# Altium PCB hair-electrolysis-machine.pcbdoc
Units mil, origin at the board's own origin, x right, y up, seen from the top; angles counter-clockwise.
Board outline 3248.4 x 4021.2 mil, 2 copper layers (Top Layer, Bottom Layer), stack 1.5 mil thick; 83 components, 64 nets, 277 pads, 40 vias.
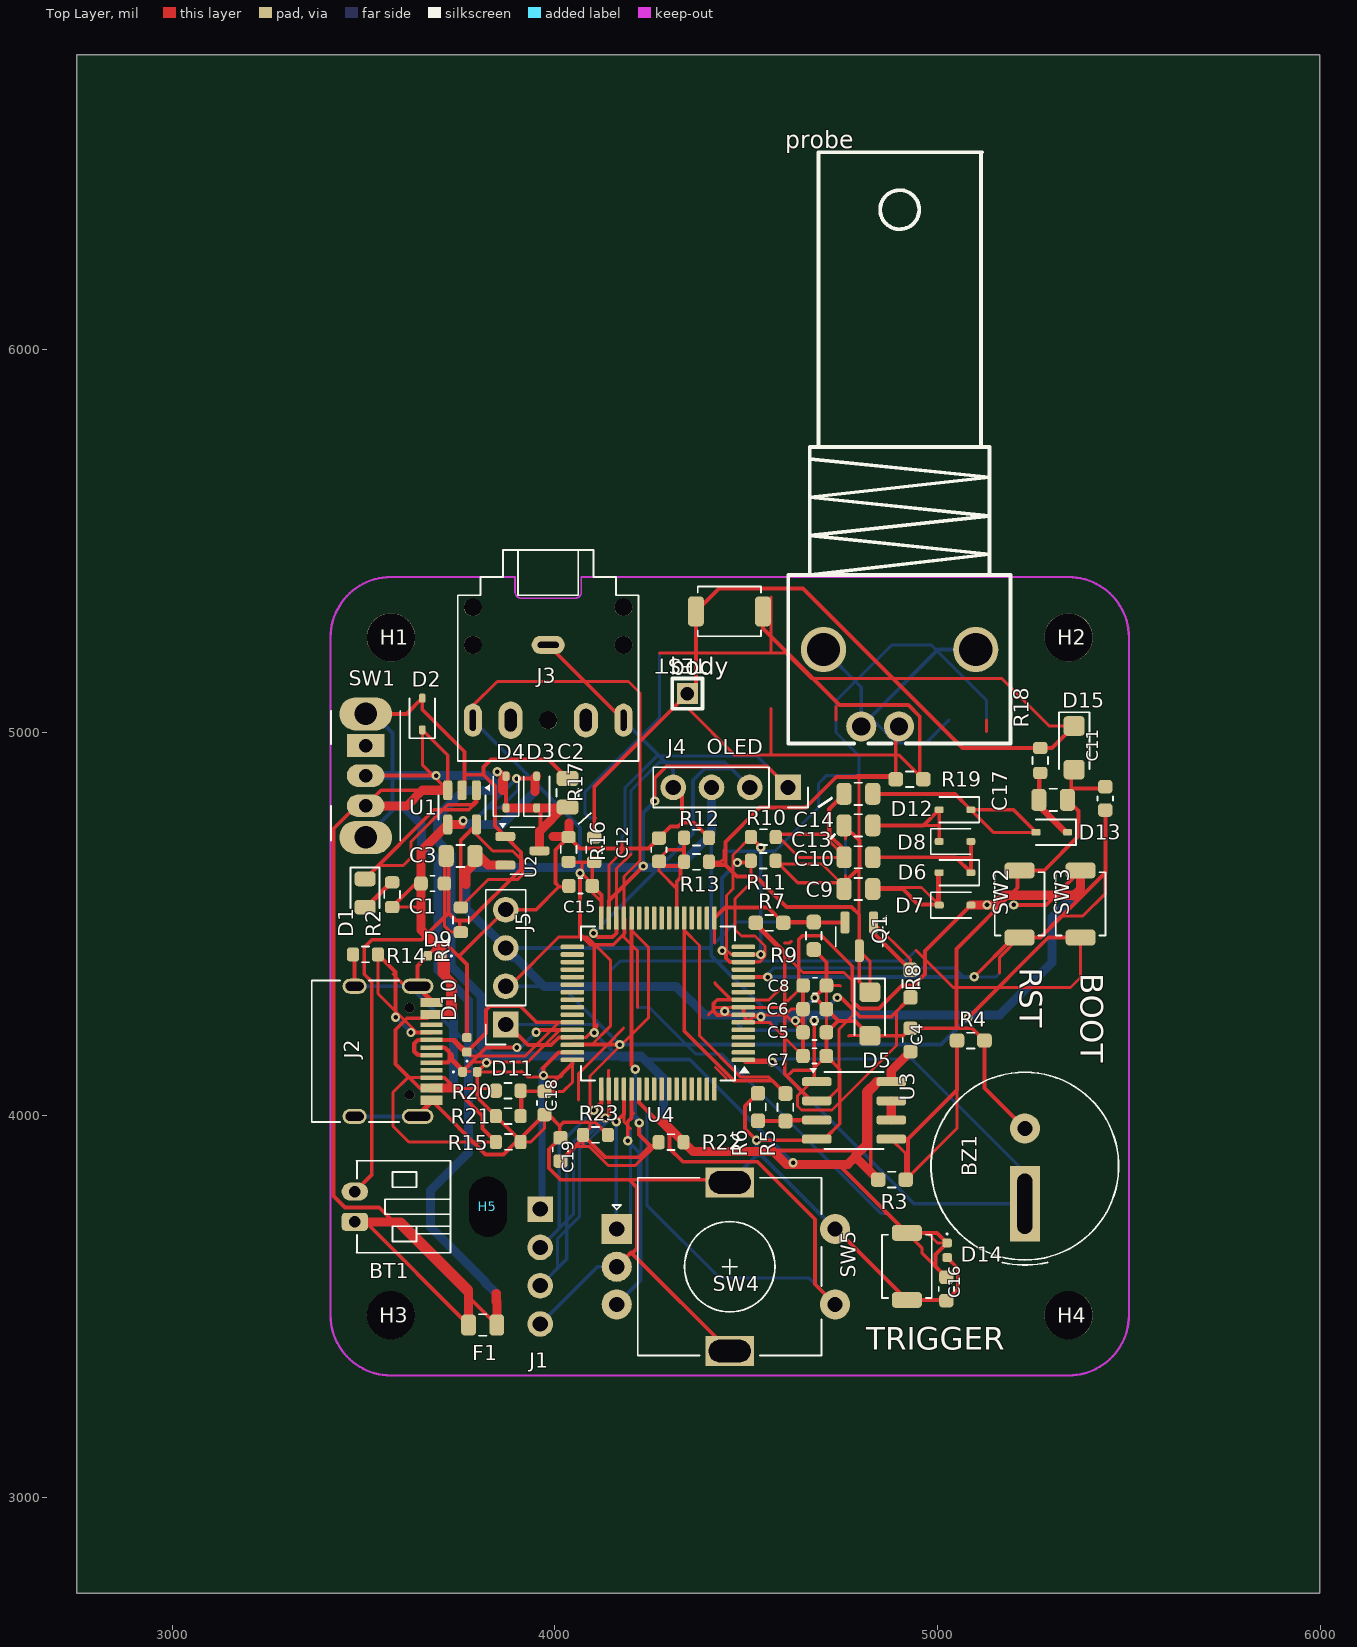
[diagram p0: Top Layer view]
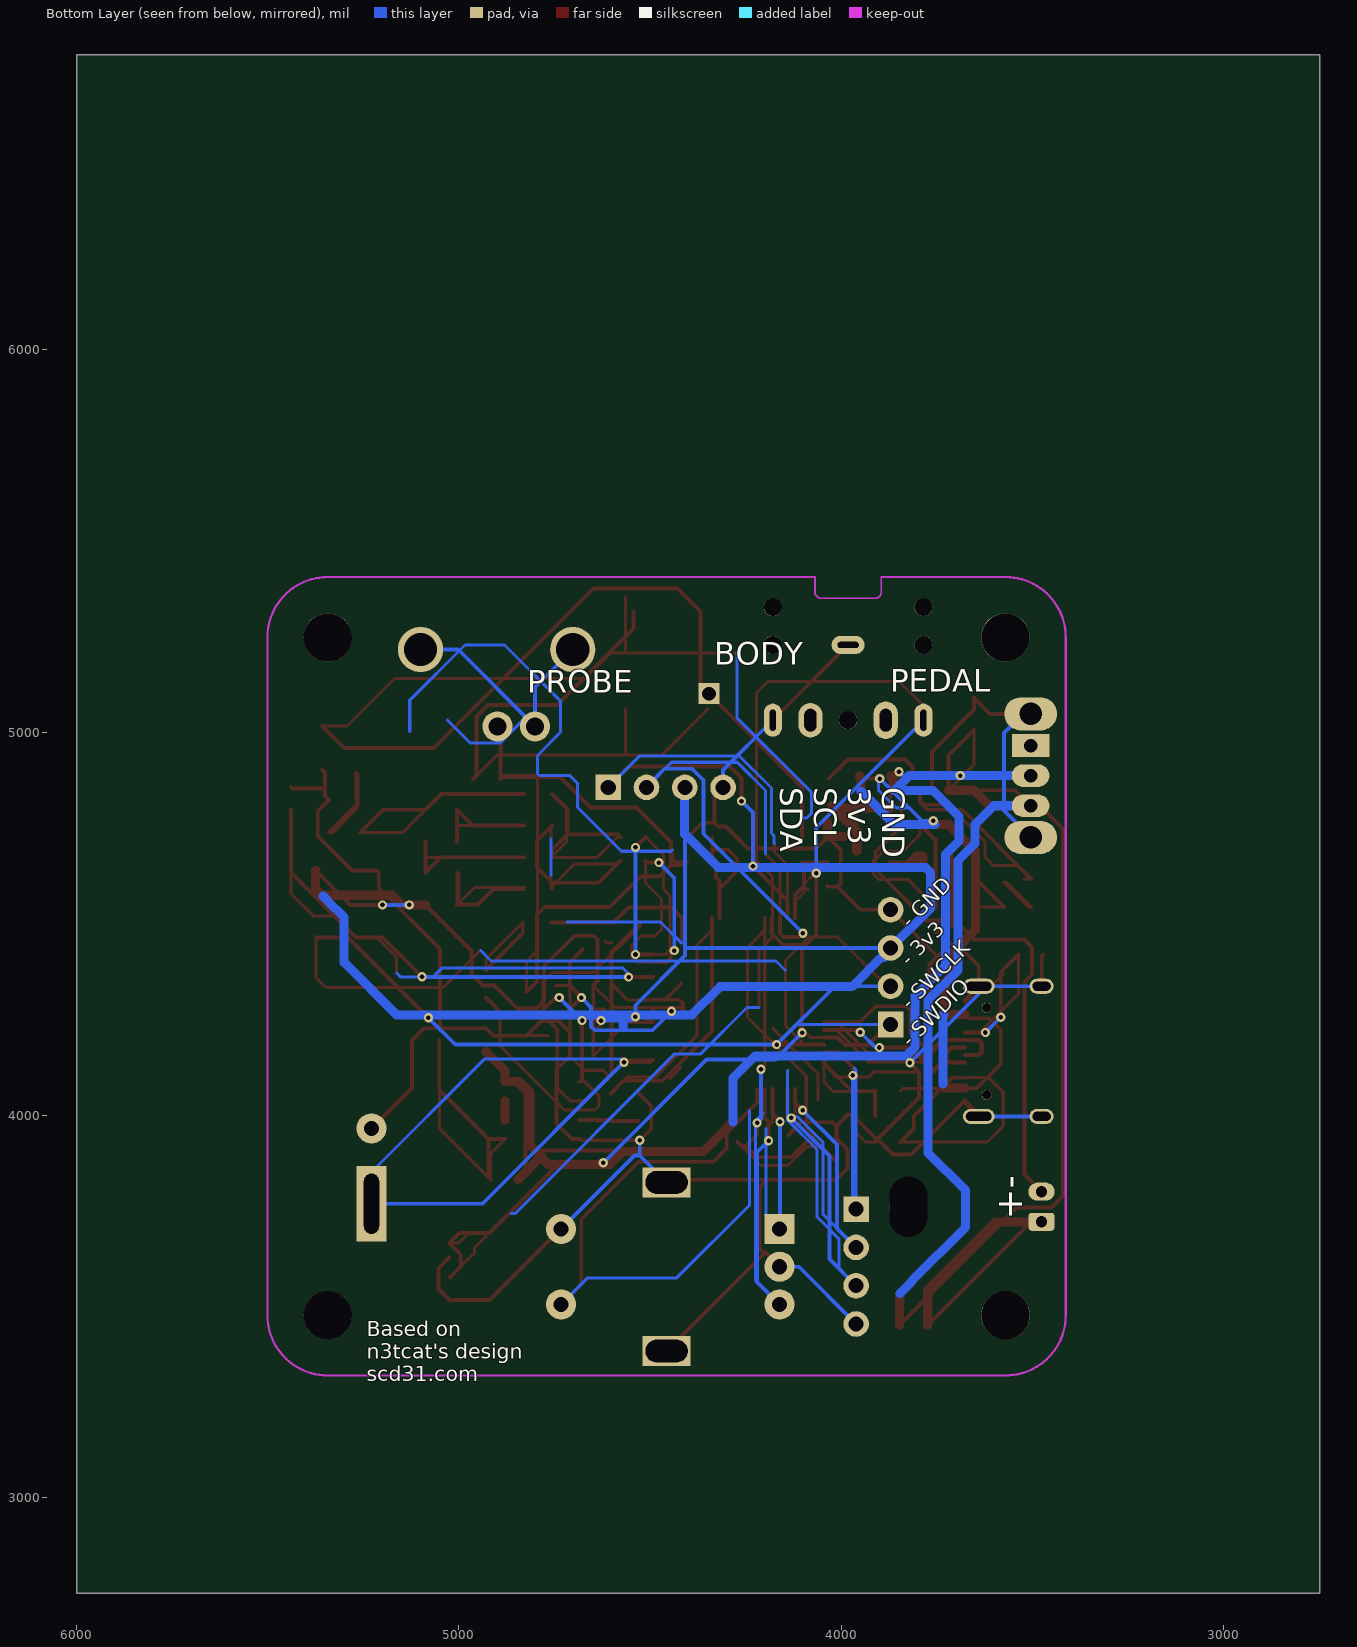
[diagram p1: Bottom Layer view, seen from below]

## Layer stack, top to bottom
Top Layer: signal copper (thickness not stored)
dielectric 1: surface 1.5, FR4, Dk 4.5
Bottom Layer: signal copper (thickness not stored)

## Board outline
5998.4,2750 2750,2750 2750,6771.2 5998.4,6771.2

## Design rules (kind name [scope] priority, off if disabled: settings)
BoardOutlineClearance copperThickness1oz [All] p0: genericclearance=10 ignorepadtopadclearanceinfootprint=FALSE except(0: Arc-SplitContinuation Track-SplitContinuation SMDPad-SplitContinuation THPad-SplitContinuation Via-SplitContinuation Fill-SplitContinuation Poly-SplitContinuation Region-SplitContinuation Text-SplitContinuation)
BoardOutlineClearance otherClearance [All] p0: genericclearance=10 ignorepadtopadclearanceinfootprint=FALSE except(0: Arc-SplitContinuation Track-SplitContinuation SMDPad-SplitContinuation THPad-SplitContinuation Via-SplitContinuation Fill-SplitContinuation Poly-SplitContinuation Region-SplitContinuation Text-SplitContinuation)
Clearance copperThickness1oz [All] p1: gap=7 ignorepadtopadclearanceinfootprint=FALSE
Clearance otherClearance [All] p1: gap=7 ignorepadtopadclearanceinfootprint=FALSE
DiffPairsRouting differentialPair [All] p1: maxuncoupledlength=10 minlimit=5 maxlimit=Infinity mostfreqgap=6 toplayer_minwidth=5 toplayer_prefwidth=100 toplayer_maxwidth=100 bottomlayer_minwidth=5 bottomlayer_prefwidth=100 bottomlayer_maxwidth=100
PasteMaskExpansion pasteMaskExpansion [All] p1: expansion=0
PlaneConnect innerPlane [All] p1: planeconnectstyle=Relief reliefexpansion=20 reliefentries=4 reliefconductorwidth=10 reliefairgap=10
PolygonConnect copper0 [All] p1: connectstyle=Relief reliefentries=4 reliefconductorwidth=19.685 polygonreliefangle="90 Angle" airgapwidth=19.685
RoutingVias viaSize [All] p1: viastyle="Through Hole" holewidth=12.0078 minholewidth=11.811 maxholewidth=248.0314 width=12.0078 minwidth=11.811 maxwidth=248.0314
SolderMaskExpansion solderMaskExpansion [IsVia] p1: useseparateexpansions=TRUE expansion=-1000 expansionbottom=-1000
SolderMaskExpansion solderMaskExpansion [All] p2: useseparateexpansions=TRUE expansion=2 expansionbottom=2
Width copperThickness1oz [All] p1: maxlimit=100 minlimit=5 preferedwidth=10

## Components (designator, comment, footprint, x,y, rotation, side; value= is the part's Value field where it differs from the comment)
body "" HDR-TH_1P-V-M_XKB_X4611WV-01I-C28D40 4345.9,5101.2 r0 top
BT1 "Device_Battery_Cell" Connector_JST:JST_PH_S2B-PH-K_1x02_P2.00mm_Horizontal 3476.8,3720.9 r90 top
BZ1 "Device_Buzzer" Buzzer_Beeper:Buzzer_TDK_PS1240P02BT_D12.2mm_H6.5mm 5228,3768.1 r90 top
C1 "Device_C_Small" Capacitor_SMD:C_0603_1608Metric#1 3680.3,4605.1 r180 top
C2 "Device_C" Capacitor_SMD:C_0805_2012Metric#1 4032.7,4842.1 r90 top
C3 "Device_C" Capacitor_SMD:C_0805_2012Metric#2 3753.1,4677.2 r180 top
C4 "Device_C_Small" Capacitor_SMD:C_0603_1608Metric#2 4929.1,4196.3 r90 top
C5 "Device_C_Small" Capacitor_SMD:C_0603_1608Metric#3 4678.7,4216.1 r0 top
C6 "Device_C_Small" Capacitor_SMD:C_0603_1608Metric#3 4678.7,4276.8 r0 top
C7 "Device_C_Small" Capacitor_SMD:C_0603_1608Metric#3 4678.7,4154.3 r0 top
C8 "Device_C_Small" Capacitor_SMD:C_0603_1608Metric#1 4679.1,4338.6 r0 top
C9 "Device_C" Capacitor_SMD:C_0805_2012Metric#1 4793.1,4590.6 r180 top
C10 "Device_C" Capacitor_SMD:C_0805_2012Metric#1 4793.1,4673.6 r180 top
C11 "Device_C_Small" Capacitor_SMD:C_0603_1608Metric#3 5438.2,4827.6 r270 top
C12 "Device_C" Capacitor_SMD:C_0603_1608Metric#1 4271.7,4693.3 r90 top
C13 "Device_C" Capacitor_SMD:C_0805_2012Metric#1 4793.1,4757.1 r180 top
C14 "Device_C" Capacitor_SMD:C_0805_2012Metric#1 4793.1,4839.4 r180 top
C15 "Device_C" Capacitor_SMD:C_0603_1608Metric#1 4066.9,4598.8 r180 top
C16 "Device_C_Small" Capacitor_SMD:C_0603_1608Metric#1 5022.8,3545.3 r90 top
C17 "Device_C" Capacitor_SMD:C_0805_2012Metric#1 5301.9,4823.6 r0 top
C18 "Device_C" Capacitor_SMD:C_0603_1608Metric#1 3972.6,4031.5 r270 top
C19 "Device_C" Capacitor_SMD:C_0603_1608Metric#1 4014.2,3910.2 r90 top
D1 "Device_LED" LED_SMD:LED_0805_2012Metric 3503.5,4580.2 r270 top
D2 "Diode_SM4001" Diode_SMD:D_SOD-323#1 3653.1,5048.1 r90 top
D3 "Diode_1N5819WS" Diode_SMD:D_SOD-323#2 3952,4844.1 r90 top
D4 "Diode_1N5819WS" Diode_SMD:D_SOD-323#2 3872,4844.1 r90 top
D5 "Diode_SMF18A" Diode_SMD:D_SMF#1 4822.8,4264.2 r270 top
D6 "Diode_1N5819WS" Diode_SMD:D_SOD-323#1 5045.6,4548.7 r0 top
D7 "Diode_1N5819WS" Diode_SMD:D_SOD-323#3 5045.5,4633.4 r180 top
D8 "Diode_1N5819WS" Diode_SMD:D_SOD-323#1 5045.5,4714.9 r0 top
D9 "Diode_SM6T7V5A" Diode_SMD:D_0402_1005Metric 3686.3,4416.1 r180 top
D10 "Diode_SM6T7V5A" Diode_SMD:D_0402_1005Metric 3769.7,4183.5 r90 top
D11 "Diode_SM6T7V5A" Diode_SMD:D_0402_1005Metric 3777.6,4112.6 r0 top
D12 "Diode_1N5819WS" Diode_SMD:D_SOD-323#3 5045.4,4797.9 r180 top
D13 "Diode_1N5819WS" Diode_SMD:D_SOD-323#3 5298.4,4739 r180 top
D14 "Diode_SM6T7V5A" Diode_SMD:D_0402_1005Metric 5024.8,3646.5 r270 top
D15 "Diode_SMF18A" Diode_SMD:D_SMF#2 5356.9,4959.7 r270 top
F1 "Device_Polyfuse" Fuse:Fuse_0805_2012Metric 3811,3451.2 r0 top
H1 "Mechanical_MountingHole" MountingHole:MountingHole_3.2mm_M3 3571.3,5248.4 r0 top
H2 "Mechanical_MountingHole" MountingHole:MountingHole_3.2mm_M3 5342.5,5248.4 r0 top
H3 "Mechanical_MountingHole" MountingHole:MountingHole_3.2mm_M3 3570.9,3476.8 r0 top
H4 "Mechanical_MountingHole" MountingHole:MountingHole_3.2mm_M3 5342.5,3476.8 r0 top
H5 "Mechanical_MountingHole" MountingHole:MountingHole_2.5mm 3824.8,3760.2 r0 top
J1 "Connector_Conn_01x04_Pin" Connector_PinHeader_2.54mm:PinHeader_1x04_P2.54mm_Vertical 3961.4,3753.9 r0 top
J2 "Connector_USB_C_Receptacle_USB2.0_16P" Connector_USB:USB_C_Receptacle_HRO_TYPE-C-31-M-12 3517.7,4166.5 r270 top
J3 "Connector_Audio_AudioJack3_SwitchTR" Connector_Audio:Jack_3.5mm_CUI_SJ1-3525N_Horizontal 3982.3,5228.7 r180 top
J4 "Connector_Conn_01x04_Pin" Connector_PinSocket_2.54mm:PinSocket_1x04_P2.54mm_Vertical 4609.1,4856.3 r270 top
J5 "Connector_Conn_01x04_Pin" Connector_PinSocket_2.54mm:PinSocket_1x04_P2.54mm_Vertical 3871.3,4236.6 r180 top
probe "3GHz" BNC-TH_DOSIN-801-0030 4900.9,5116.2 r0 top
Q1 "Transistor_FET_BSS138" Package_TO_SOT_SMD:SOT-23 4795.3,4466.4 r270 top
R1 "Device_R" Resistor_SMD:R_0603_1608Metric#1 3753.9,4510.2 r90 top
R2 "Device_R" Resistor_SMD:R_0603_1608Metric#2 3574.4,4575.8 r270 top
R3 "Device_R" Resistor_SMD:R_0603_1608Metric_Pad0.98x0.95mm_HandSolder#1 4880.6,3831.1 r0 top
R4 "Device_R" Resistor_SMD:R_0603_1608Metric_Pad0.98x0.95mm_HandSolder#1 5086.6,4194.5 r0 top
R5 "Device_R" Resistor_SMD:R_0603_1608Metric_Pad0.98x0.95mm_HandSolder#1 4602.4,4020.1 r90 top
R6 "Device_R" Resistor_SMD:R_0603_1608Metric_Pad0.98x0.95mm_HandSolder#2 4530.5,4021 r270 top
R7 "Device_R" Resistor_SMD:R_0603_1608Metric_Pad0.98x0.95mm_HandSolder#2 4560.5,4502.4 r0 top
R8 "Device_R" Resistor_SMD:R_0603_1608Metric_Pad0.98x0.95mm_HandSolder#1 4929.1,4343.4 r270 top
R9 "Device_R" Resistor_SMD:R_0603_1608Metric_Pad0.98x0.95mm_HandSolder#1 4676.4,4468.5 r90 top
R10 "Device_R" Resistor_SMD:R_0603_1608Metric#2 4544.5,4726.4 r0 top
R11 "Device_R" Resistor_SMD:R_0603_1608Metric#2 4544.3,4664.6 r0 top
R12 "Device_R_Small" Resistor_SMD:R_0603_1608Metric#2 4370.1,4661.8 r180 top
R13 "Device_R_Small" Resistor_SMD:R_0603_1608Metric#2 4370.1,4724.8 r0 top
R14 "Device_R" Resistor_SMD:R_0603_1608Metric#2 3504.7,4419.7 r180 top
R15 "Device_R" Resistor_SMD:R_0603_1608Metric#3 3878,3929.5 r0 top
R16 "Device_R_Small" Resistor_SMD:R_0603_1608Metric#2 4102.4,4693.3 r270 top
R17 "Device_R_Small" Resistor_SMD:R_0603_1608Metric#2 4035.4,4694.3 r90 top
R18 "Device_R" Resistor_SMD:R_0603_1608Metric#2 5268.3,4926.8 r90 top
R19 "Device_R" Resistor_SMD:R_0603_1608Metric_Pad0.98x0.95mm_HandSolder#2 4926.8,4877.6 r180 top
R20 "Device_R_Small" Resistor_SMD:R_0603_1608Metric#3 3877.8,4063.4 r0 top
R21 "Device_R_Small" Resistor_SMD:R_0603_1608Metric#1 3877.8,3997.2 r180 top
R22 "Device_R_Small" Resistor_SMD:R_0603_1608Metric#3 4303.5,3929.1 r180 top
R23 "Device_R_Small" Resistor_SMD:R_0603_1608Metric#2 4105.9,3948 r0 top
SW1 "Switch_SW_SPDT" Button_Switch_THT:SW_Slide_SPDT_Angled_CK_OS102011MA1Q 3505.1,4965.7 r270 top
SW2 "Switch_SW_Push" Button_Switch_SMD:SW_SPST_TS-1088-xR025 5214.2,4551.6 r90 top
SW3 "Switch_SW_Push" Button_Switch_SMD:SW_SPST_TS-1088-xR025 5373.6,4551.6 r90 top
SW4 "Device_RotaryEncoder_Switch" Rotary_Encoder:RotaryEncoder_Alps_EC11E-Switch_Vertical_H20mm 4161.4,3702 r0 top
SW5 "Switch_SW_Push" Button_Switch_SMD:SW_SPST_TS-1088-xR025 4919.7,3604.3 r90 top
TEST "Switch_SW_Push" Button_Switch_SMD:SW_SPST_TS-1088-xR025 4455.9,5316.2 r180 top
U1 "Battery_Management_MCP73831-2-OT" Package_TO_SOT_SMD:SOT-23-5 3757.1,4804 r270 top
U2 "Regulator_Linear_XC6206PxxxMR" Package_TO_SOT_SMD:SOT-23-3 3915,4690.6 r0 top
U3 "Amplifier_Operational_LM358" Package_SO:SOIC-8_3.9x4.9mm_P1.27mm 4781.5,4012 r0 top
U4 "MCU_ST_STM32G0_STM32G0B1RBTx" Package_QFP:LQFP-64_10x10mm_P0.5mm 4268.9,4291.5 r180 top

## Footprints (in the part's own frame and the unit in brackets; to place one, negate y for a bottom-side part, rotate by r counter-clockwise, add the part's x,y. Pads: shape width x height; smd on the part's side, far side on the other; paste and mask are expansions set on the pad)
BNC-TH_DOSIN-801-0030 [mil]
  round 78.7 hole 47.2: 1(-2,-100.4) 2(-100.4,-100.4)
  round 118.1 hole 86.6: 3(-198.9,100.4) 4(198.8,100.4)
  silkscreen extent -291,-145 290,1400
Button_Switch_SMD:SW_SPST_TS-1088-xR025 [mil]
  rrect47% 41.3x78.7 smd paste+0 mask+0: 1(-87.6,0) 2(87.6,0)
  silkscreen extent -83,-65 83,65
Button_Switch_THT:SW_Slide_SPDT_Angled_CK_OS102011MA1Q [mil]
  rect 59.1x98.4 hole 35.4 paste+0 mask+0: 1(0,0)
  oval 59.1x98.4 hole 35.4 paste+0 mask+0: 2(78.7,0) 3(157.4,0)
  oval 86.6x137.8 hole 59.1 paste+0 mask+0: MP(-82.7,0) MP(240.1,0)
  silkscreen extent -91,-91 248,91
Buzzer_Beeper:Buzzer_TDK_PS1240P02BT_D12.2mm_H6.5mm [mil]
  rect 196.9x78.7 hole 39.4 slot 157.5 at 0 deg paste+0 mask+0: 1(0,0)
  round 78.7 hole 39.4 paste+0 mask+0: 2(196.9,0)
  silkscreen extent -160,-245 344,245
Capacitor_SMD:C_0603_1608Metric#1 [mil]
  rrect50% 35.4x37.4 smd paste+0 mask+0: 1(-30.5,0) 2(30.5,0)
  silkscreen extent -6,-20 6,20
Capacitor_SMD:C_0603_1608Metric#2 [mil]
  rrect50% 35.4x37.4 smd paste+0 mask+0: 1(-30.6,0) 2(30.5,0)
  silkscreen extent -6,-20 6,20
Capacitor_SMD:C_0603_1608Metric#3 [mil]
  rrect50% 35.4x37.4 smd paste+0 mask+0: 1(-30.5,0) 2(30.6,0)
  silkscreen extent -6,-20 6,20
Capacitor_SMD:C_0805_2012Metric#1 [mil]
  rrect50% 39.4x57.1 smd paste+0 mask+0: 1(-37.4,0) 2(37.4,0)
  silkscreen extent -10,-29 10,29
Capacitor_SMD:C_0805_2012Metric#2 [mil]
  rrect50% 39.4x57.1 smd paste+0 mask+0: 1(-37.5,0) 2(37.4,0)
  silkscreen extent -10,-29 10,29
Connector_Audio:Jack_3.5mm_CUI_SJ1-3525N_Horizontal [mil]
  oval 47.2x86.6 hole 15.7 slot 55.1 at 90 deg paste+0 mask+0: R(-196.8,196.8) T(196.9,196.8)
  oval 63x90.6 hole 31.5 slot 59.1 at 90 deg paste+0 mask+0: RN(-98.4,196.8)
  oval 86.6x47.2 hole 15.7 slot 55.1 at 0 deg paste+0 mask+0: S(0,0)
  oval 63x98.4 hole 31.5 slot 59.1 at 90 deg paste+0 mask+0: TN(98.4,196.8)
  round 47.2 hole 47.2 unplated paste+0 mask+0: ""(-196.8,-98.5) ""(-196.8,0) ""(0,196.8) ""(196.9,-98.5) ""(196.9,0)
  Board Outline Layer lines w4.7: 255.9,-177.2 86.6,-177.2 86.6,-137.8 86.2,-134.3 85.1,-131 83.2,-128 80.7,-125.5 77.7,-123.6 74.4,-122.5 70.9,-122.1 -70.8,-122.1 -74.4,-122.5 -77.7,-123.6 -80.7,-125.5 -83.2,-128 -85,-131 -86.2,-134.3 -86.6,-137.8 -86.6,-177.2 -255.9,-177.2
  silkscreen extent -236,-248 236,303
Connector_JST:JST_PH_S2B-PH-K_1x02_P2.00mm_Horizontal [mil]
  rrect41% 47.2x68.9 hole 29.5 paste+0 mask+0: 1(0,0)
  oval 47.2x68.9 hole 29.5 paste+0 mask+0: 2(78.7,0)
  silkscreen extent -81,-250 160,-4
Connector_PinHeader_2.54mm:PinHeader_1x04_P2.54mm_Vertical [mil]
  rect 66.9x66.9 hole 39.4 paste+0 mask+0: 1(0,0)
  round 66.9 hole 39.4 paste+0 mask+0: 2(0,-100) 3(0,-200) 4(0,-300)
Connector_PinSocket_2.54mm:PinSocket_1x04_P2.54mm_Vertical [mil]
  rect 66.9x66.9 hole 39.4 paste+0 mask+0: 1(0,0)
  round 66.9 hole 39.4 paste+0 mask+0: 2(0,-100) 3(0,-200) 4(0,-300)
  silkscreen extent -52,-352 52,52
Connector_USB:USB_C_Receptacle_HRO_TYPE-C-31-M-12 [mil]
  rect 23.6x57.1 smd paste+0 mask+0: A1(-128,159.3) A4(-96.5,159.3) A9(96.4,159.3) A12(127.9,159.3) B1(127.9,159.3) B4(96.4,159.3) B9(-96.5,159.3) B12(-128,159.3)
  rect 11.8x57.1 smd paste+0 mask+0: A5(-49.2,159.3) A6(-9.9,159.3) A7(9.8,159.3) A8(49.2,159.3) B5(68.9,159.3) B6(29.5,159.3) B7(-29.6,159.3) B8(-68.9,159.3)
  oval 39.4x82.7 hole 23.6 slot 66.9 at 90 deg paste+0 mask+0: S1(-170.1,123.2) S1(170,123.2)
  oval 39.4x63 hole 23.6 slot 47.2 at 90 deg paste+0 mask+0: S1(-170.1,-41.3) S1(170,-41.3)
  round 25.6 hole 25.6 unplated paste+0 mask+0: ""(-113.8,102.4) ""(113.7,102.4)
  silkscreen extent -185,-154 185,75
Diode_SMD:D_0402_1005Metric [mil]
  rrect50% 23.2x25.2 smd paste+0 mask+0: 1(-19.1,0) 2(19.1,0)
  silkscreen extent -45,-2 -41,2
Diode_SMD:D_SMF#1 [mil]
  rrect38% 51.2x55.1 smd paste+0 mask+0: 1(-57.1,0) 2(57.1,0)
  silkscreen extent -93,-40 55,40
Diode_SMD:D_SMF#2 [mil]
  rrect38% 51.2x55.1 smd paste+0 mask+0: 1(-57.1,0) 2(57,0)
  silkscreen extent -93,-40 55,40
Diode_SMD:D_SOD-323#1 [mil]
  rrect50% 23.6x17.7 smd paste+0 mask+0: 1(-41.3,0) 2(41.4,0)
  silkscreen extent -63,-34 41,33
Diode_SMD:D_SOD-323#2 [mil]
  rrect50% 23.6x17.7 smd paste+0 mask+0: 1(-41.3,0) 2(41.3,0)
  silkscreen extent -63,-33 41,34
Diode_SMD:D_SOD-323#3 [mil]
  rrect50% 23.6x17.7 smd paste+0 mask+0: 1(-41.4,0) 2(41.3,0)
  silkscreen extent -63,-33 41,34
Fuse:Fuse_0805_2012Metric [mil]
  rrect50% 38.4x55.1 smd paste+0 mask+0: 1(-36.9,0) 2(36.9,0)
  silkscreen extent -10,-28 10,28
HDR-TH_1P-V-M_XKB_X4611WV-01I-C28D40 [mil]
  rect 55.1x55.1 hole 35.4: 1(0,0)
  silkscreen extent -39,-39 39,39
LED_SMD:LED_0805_2012Metric [mil]
  rrect50% 38.4x55.1 smd paste+0 mask+0: 1(-36.9,0) 2(36.9,0)
  silkscreen extent -66,-38 39,38
MountingHole:MountingHole_2.5mm [mil]
  round 98.4 hole 98.4 slot 157.5 at 90 deg unplated paste+0 mask+0: ""(0,0)
MountingHole:MountingHole_3.2mm_M3 [mil]
  round 126 hole 126 unplated paste+0 mask+0: ""(0,0)
Package_QFP:LQFP-64_10x10mm_P0.5mm [mil]
  rrect50% 61x11.8 smd paste+0 mask+0: 1(-223.4,147.6) 2(-223.4,127.9) 3(-223.4,108.2) 4(-223.4,88.5) 5(-223.4,68.9) 6(-223.4,49.2) 7(-223.4,29.5) 8(-223.4,9.8) 9(-223.4,-9.9) 10(-223.4,-29.6) 11(-223.4,-49.2) 12(-223.4,-68.9) 13(-223.4,-88.6) 14(-223.4,-108.3) 15(-223.4,-128) 16(-223.4,-147.7) 33(223.4,-147.7) 34(223.4,-128) 35(223.4,-108.3) 36(223.4,-88.6) 37(223.4,-68.9) 38(223.4,-49.2) 39(223.4,-29.6) 40(223.4,-9.9) 41(223.4,9.8) 42(223.4,29.5) 43(223.4,49.2) 44(223.4,68.9) 45(223.4,88.5) 46(223.4,108.2) 47(223.4,127.9) 48(223.4,147.6)
  rrect50% 11.8x61 smd paste+0 mask+0: 17(-147.6,-223.5) 18(-128,-223.5) 19(-108.3,-223.5) 20(-88.6,-223.5) 21(-68.9,-223.5) 22(-49.2,-223.5) 23(-29.5,-223.5) 24(-9.8,-223.5) 25(9.8,-223.5) 26(29.5,-223.5) 27(49.2,-223.5) 28(68.9,-223.5) 29(88.6,-223.5) 30(108.3,-223.5) 31(128,-223.5) 32(147.6,-223.5) 49(147.6,223.4) 50(128,223.4) 51(108.3,223.4) 52(88.6,223.4) 53(68.9,223.4) 54(49.2,223.4) 55(29.5,223.4) 56(9.8,223.4) 57(-9.8,223.4) 58(-29.5,223.4) 59(-49.2,223.4) 60(-68.9,223.4) 61(-88.6,223.4) 62(-108.3,223.4) 63(-128,223.4) 64(-147.6,223.4)
  silkscreen extent -240,-201 201,201
Package_SO:SOIC-8_3.9x4.9mm_P1.27mm [mil]
  rrect50% 76.8x23.6 smd paste+0 mask+0: 1(-97.4,75) 2(-97.4,25) 3(-97.4,-25) 4(-97.4,-75) 5(97.4,-75) 6(97.4,-25) 7(97.4,25) 8(97.4,75)
  silkscreen extent -116,-101 77,110
Package_TO_SOT_SMD:SOT-23 [mil]
  rrect50% 58.1x23.6 smd paste+0 mask+0: 1(-36.9,37.4) 2(-36.9,-37.4) 3(36.9,0)
  silkscreen extent -55,-61 26,72
Package_TO_SOT_SMD:SOT-23-3 [mil]
  rrect50% 52.2x23.6 smd paste+0 mask+0: 1(-44.8,37.4) 2(-44.8,-37.5) 3(44.7,0)
  silkscreen extent -61,-62 32,72
Package_TO_SOT_SMD:SOT-23-5 [mil]
  rrect50% 52.2x23.6 smd paste+0 mask+0: 1(-44.8,37.4) 2(-44.8,0) 3(-44.8,-37.4) 4(44.7,-37.4) 5(44.7,37.4)
  silkscreen extent -61,-61 32,72
Resistor_SMD:R_0603_1608Metric#1 [mil]
  rrect50% 31.5x37.4 smd paste+0 mask+0: 1(-32.4,0) 2(32.5,0)
  silkscreen extent -9,-21 9,20
Resistor_SMD:R_0603_1608Metric#2 [mil]
  rrect50% 31.5x37.4 smd paste+0 mask+0: 1(-32.5,0) 2(32.5,0)
  silkscreen extent -9,-21 9,21
Resistor_SMD:R_0603_1608Metric#3 [mil]
  rrect50% 31.5x37.4 smd paste+0 mask+0: 1(-32.5,0) 2(32.4,0)
  silkscreen extent -9,-20 9,21
Resistor_SMD:R_0603_1608Metric_Pad0.98x0.95mm_HandSolder#1 [mil]
  rrect50% 38.4x37.4 smd paste+0 mask+0: 1(-35.9,0) 2(35.9,0)
  silkscreen extent -10,-21 10,21
Resistor_SMD:R_0603_1608Metric_Pad0.98x0.95mm_HandSolder#2 [mil]
  rrect50% 38.4x37.4 smd paste+0 mask+0: 1(-35.9,0) 2(36,0)
  silkscreen extent -10,-21 10,21
Rotary_Encoder:RotaryEncoder_Alps_EC11E-Switch_Vertical_H20mm [mil]
  rect 78.7x78.7 hole 39.4 paste+0 mask+0: A(0,0)
  round 78.7 hole 39.4 paste+0 mask+0: B(0,-196.9) C(0,-98.5) S1(570.9,-196.9) S2(570.9,0)
  rect 126x78.7 hole 59.1 slot 110.2 at 0 deg paste+0 mask+0: MP(295.3,-318.9) MP(295.3,122)
  silkscreen extent -12,-331 536,134

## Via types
v1: diameter 24, hole 12, Top Layer to Bottom Layer, 40 vias

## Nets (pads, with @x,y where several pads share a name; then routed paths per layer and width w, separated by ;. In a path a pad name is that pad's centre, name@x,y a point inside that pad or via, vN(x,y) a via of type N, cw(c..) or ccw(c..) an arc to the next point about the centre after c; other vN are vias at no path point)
$2I7\$4N1: D2.1 F1.2 SW1.3 U1.3 | length 2052.6
  Top Layer w10: D2.1@3653.2,5006.8 3719.7,4940.3 U1.3 3545.7,4848.8 SW1.3 3480.9,4808.3 3420.9,4748.3 3420.9,3788.3 3450.9,3758.3 3540.8,3758.3 F1.2
$2I7\$4N4: D1.1 U1.1 | length 405.2
  Top Layer w10: D1.1 3684.1,4797.7 3774.5,4797.7 3794.5,4817.7 U1.1
$2I7\$4N5: D1.2 R2.1 | length 97.9
  Top Layer w10: D1.2 3509.5,4543.3 R2.1
$2I7\$4N11: BT1.1 F1.1 | length 409
  Top Layer w10: BT1.1 3504.4,3720.9 F1.1
$2I7\$4N18: R1.2 U1.5 | length 233.4
  Top Layer w10: R1.2 3753.9,4718.7 U1.5
$2I7\power_+3.3V: C3.1 U2.2
$2I7\POWER_+3.3V:  | length 89.6
  Top Layer w10: 3790.6,4677.2 3814.6,4653.1 3870.2,4653.1
$2I7\power_+5V: C1.2 D3.2 R2.2 U1.4
$2I7\POWER_+5V:  | length 568.7
  Top Layer w10: 3574.4,4543.3 3636.2,4605.1 3649.8,4605.1 3649.8,4689.4 3719.7,4759.3 3749.7,4759.3 v1(3759.7,4769.3) ; v1(3899.7,4879.3) 3945.8,4879.3 3952,4885.4
  Bottom Layer w10: v1(3759.7,4769.3) 3789.7,4769.3 v1(3899.7,4879.3)
$2I7\power_+BATT: C2.1 D3.1 D4.1 D4.2 SW1.2 U2.3
$2I7\POWER_+BATT:  | length 733.1
  Top Layer w10: 3505.1,4887 v1(3689.3,4887) ; v1(3849.3,4897) 3860.5,4897 3872,4885.4 3872,4802.8 3952,4802.8 4030.7,4802.8 4032.7,4804.7 ; 3959.7,4690.6 3962,4692.8 3962,4802.8
  Bottom Layer w10: v1(3689.3,4887) 3839.3,4887 v1(3849.3,4897)
$2I7\power_GND: BT1.2 C1.1 C2.2 C3.2 D2.2 R1.1 SW1.MP U1.2 U2.1
$2I7\POWER_GND:  | length 2822.7
  Top Layer w10: 3476.8,3799.6 3521.3,3844.1 3521.3,4348 3501.3,4368 3501.3,4438 3521.3,4458 3651.3,4458 3721.3,4528 ; 3505.1,5048.4 3612.1,5048.4 3653.2,5089.5 3653.2,5059.5 3763.2,4949.5 3763.2,4854.9 3757.1,4848.8 ; 3710.8,4605.1 3721.3,4608 ; 3715.7,4677.2 3721.3,4671.6 3721.3,4528 ; 3751.3,4508 3751.3,4480.4 3753.9,4477.8 ; 3763.2,4889.5 3813.2,4889.5 ; 4032.7,4879.5 3982.7,4929.5 3833.2,4929.5 3813.2,4909.5 3813.2,4889.5 ; 3721.3,4528 3741.3,4508 3777,4508 3911.3,4642.3 3911.3,4686.8 3870.2,4728 3843.2,4755 3843.2,4859.5 3813.2,4889.5
  Bottom Layer w10: 3505.1,4725.6 3575.1,4795.6 3575.1,4998.4 3525.1,5048.4 3505.1,5048.4
$2I8\$3N3: R7.1 U3.2 | length 539.3
  Top Layer w10: R7.1 4600.6,4426.3 4600.6,4107 4670.6,4037 U3.2
$2I8\$3N7: C13.1 D8.1 D12.2 | length 273.4
  Top Layer w10: C13.1 4963.2,4757.1 D12.2 D8.1@5004.1,4715
$2I8\$3N10: C14.1 D12.1 D13.2 | length 468.2
  Top Layer w10: C14.1 5045.3,4839.4 D12.1 5198.1,4797.9 D13.2
$2I8\$3N12: C9.1 D6.1 D7.2 | length 275.1
  Top Layer w10: C9.1 4909.2,4590.6 4949.2,4550.6 D6.1@5000.5,4550.6 ; D7.2 5000.5,4629.6 D6.1@5000.5,4550.6 ; D6.1 D6.1@5000.5,4550.6
$2I8\$3N23: J2.A5 R14.1 | length 293.3
  Top Layer w10: R14.1 3583.4,4373.5 v1(3583.4,4255.7) ; v1(3623.4,4215.7) J2.A5
  Bottom Layer w10: v1(3583.4,4255.7) v1(3623.4,4215.7)
$2I8\$3N27: J2.B5 R15.1 | length 257.5
  Top Layer w10: J2.B5 3710.5,4097.6 3810.5,3997.6 3810.5,3964.5 R15.1
$2I8\$3N34: R5.1 R6.2 U3.3 | length 155.1
  Top Layer w10: R6.2 4531.4,3984.2 R5.1 4605.2,3987 U3.3
$2I8\$3N37: C10.1 D7.1 D8.2 | length 354.5
  Top Layer w10: C10.1 5046.6,4673.6 D7.1 D8.2
$2I8\$3N44: Q1.1 R8.1 | length 163.9
  Top Layer w10: Q1.1 4832.7,4475.8 R8.1
$2I8\$3N50: C9.2 C13.2 R11.2 | length 402.4
  Top Layer w10: R11.2 4634.3,4607.1 C9.2@4755.7,4607.1 ; C9.2 C9.2@4755.7,4607.1 ; C13.2 4795.7,4717.1 4795.7,4647.1 C9.2@4755.7,4607.1
$2I8\$3N61: C10.2 C14.2 R10.2 | length 340.6
  Top Layer w10: R10.2 4584.2,4733.6 4715.7,4733.6 ; C10.2 4755.7,4693.6 4715.7,4733.6 ; C14.2 4715.7,4799.4 4715.7,4733.6
$2I8\$3N64: U3.6 U3.7 | length 50
  Top Layer w10: U3.6 U3.7
$2I8\$3N80: C17.1 D13.1 R18.1 | length 188.1
  Top Layer w10: R18.1 5264.5,4890.5 C17.1 5264.5,4814.3 D13.1
$2I8\$3N84: R19.1 TEST.1 | length 717.7
  Top Layer w10: TEST.1 4543.5,5271.8 4743.5,5071.8 4923.5,5071.8 4953.5,5041.8 4953.5,4886.8 R19.1
$2I8\$3N88: R3.2 R4.1 U3.5 | length 462.5
  Top Layer w10: U3.5 4922.4,3937 ; R3.2 4922.4,3836.9 4922.4,3937 ; R4.1 5050.7,4065.3 4922.4,3937
$2I8\$3N105: R8.2 U3.1 | length 480.8
  Top Layer w10: v1(4677.5,4247) 4677.5,4093.6 U3.1 ; v1(4737.5,4307) 4747.5,4307 4797.5,4257 4878.7,4257 R8.2
  Bottom Layer w10: v1(4677.5,4247) v1(4737.5,4307)
$2I8\BATT_SENSE: C19.1 R22.2 R23.1 U4.28 | length 947.5
  Top Layer w10: C19.1 4073.4,3939 R23.1 4132,3889.4 4220,3889.4 4250,3919.4 ; U4.28 4200,4129.4 v1(4210,4119.4) ; v1(4220,3979.4) 4220,3949.4 4250,3919.4 ; R22.2 4261.4,3919.4 4250,3919.4
  Bottom Layer w10: v1(4210,4119.4) 4210,3989.4 v1(4220,3979.4)
$2I8\BODY_ELECTRODE: body.1 D15.1 R16.1 R18.2 TEST.2 | length 1910.5
  Top Layer w10: R16.1 4102.4,4857.7 body.1 4368.3,5123.6 TEST.2 4428.3,5376.2 4648.3,5376.2 5065.2,4959.3 R18.2 5299.3,4959.3 D15.1
$2I8\BOOT: J5.2 SW3.1 U4.46 | length 1805.5
  Top Layer w10: U4.46 4046.2,4184 v1(4169.2,4184) ; v1(5079.2,4254) 5289.2,4464 SW3.1
  Bottom Layer w10: J5.2 4016.6,4336.6 v1(4169.2,4184) 5009.2,4184 v1(5079.2,4254)
$2I8\BTN_OK: SW4.S1 U4.54 | length 889.6
  Top Layer w10: U4.54 4219.7,4032.6 4299.7,3952.6 4299.7,3912.6 4334.5,3877.7 4529.7,3877.7 4679.7,3727.7 4679.7,3557.7 SW4.S1
$2I8\BUZZER1: BZ1.1 U4.1 | length 891.4
  Top Layer w10: U4.1 4498.1,4138.1 v1(4568,4138.1)
  Bottom Layer w10: v1(4568,4138.1) 4938,3768.1 BZ1.1
$2I8\CHARGE_PUMP_OSC0: R10.1 U4.15 | length 363.2
  Top Layer w10: U4.15 v1(4537.9,4419.5) ; R10.1 4537.9,4700.5 v1(4537.9,4699.5)
  Bottom Layer w10: v1(4537.9,4419.5) v1(4537.9,4699.5)
$2I8\CHARGE_PUMP_OSC1: R11.1 U4.14 | length 357.3
  Top Layer w10: v1(4436.8,4429.8) 4446.8,4419.8 4446.8,4409.8 4456.8,4399.8 U4.14 ; v1(4476.8,4659.8) 4507,4659.8 R11.1
  Bottom Layer w10: v1(4436.8,4429.8) 4436.8,4619.8 v1(4476.8,4659.8)
$2I8\CURRENT_SENSE: Q1.2 R7.2 R9.2 U4.17 | length 370.6
  Top Layer w10: U4.17 4443.9,4542.4 4556.5,4542.4 R7.2 4598.5,4504.4 R9.2 4677.5,4503.3 Q1.2
$2I8\D+: D11.1 J2.A6 J2.B6 U4.44 | length 504.9
  Top Layer w10: J2.B6 3721.1,4137 3730.5,4146.4 ; J2.A6 3710.5,4176.4 3730.5,4156.4 3730.5,4146.4 ; D11.1 D11.1@3760.5,4116.4 ; v1(3900.5,4176.4) 3820.5,4176.4 D11.1@3760.5,4116.4 ; v1(3950.5,4216.4) 3956.8,4222.6 U4.44 ; 3730.5,4146.4 D11.1@3760.5,4116.4
  Bottom Layer w10: v1(3900.5,4176.4) 3910.5,4176.4 v1(3950.5,4216.4)
$2I8\D-: D10.1 J2.A7 J2.B7 U4.43 | length 599.2
  Top Layer w10: J2.A7 3643.4,4156.7 3633.4,4166.7 3633.4,4186.7 3642.8,4196.1 J2.B7 3738,4196.1 D10.1 3819.7,4214.4 3819.7,4274.4 3829.7,4284.4 3909.7,4284.4 3951.7,4242.3 U4.43
$2I8\DAC_OUT1: R5.2 U4.21 | length 627.9
  Top Layer w10: U4.21 4337.8,4219.4 4467.8,4089.4 4568.9,4089.4 R5.2
$2I8\FOLLICLE_ELECTRODE: D5.1 probe.1 Q1.3 R12.1 R19.2 | length 1383.6
  Top Layer w10: R12.1 4410.8,4653.6 4445.3,4653.6 ; D5.1 4795.3,4348.8 Q1.3 4795.3,4523.6 4775.3,4543.6 4605.3,4543.6 4525.3,4623.6 4475.3,4623.6 4445.3,4653.6 ; probe.1 4890.8,5007.7 R19.2 4884.8,4883.6 4735.3,4883.6 4655.3,4803.6 4535.3,4803.6 4445.3,4713.6 4445.3,4653.6
$2I8\I2C2_SCL: J4.2 U4.30 | length 797.5
  Top Layer w10: v1(4100.6,4475) 4110.6,4465 4150.6,4465 4160.6,4475 U4.30
  Bottom Layer w10: v1(4100.6,4475) 4360.6,4735 4360.6,4875 4390.6,4905 4461.7,4905 J4.2
$2I8\I2C2_SDA: J4.1 U4.31 | length 798.3
  Top Layer w10: U4.31 4140.9,4560.5 v1(4230.9,4650.5) ; v1(4260.9,4820.5) 4260.9,4880.5 4290.9,4910.5 4554.9,4910.5 J4.1
  Bottom Layer w10: v1(4230.9,4650.5) 4230.9,4790.5 v1(4260.9,4820.5)
$2I8\OUTPUT_HIGH: C15.1 R16.2 R17.1 U4.32 | length 225.2
  Top Layer w10: R17.1 4036.4,4660.8 R16.2 4097.4,4655.9 C15.1 4121.3,4575 U4.32
$2I8\OUTPUT_LOW: C12.1 R12.2 R13.1 U4.22 | length 278.9
  Top Layer w10: C12.1 4284,4650.5 R12.2@4328.1,4650.5 ; U4.22 4318.1,4610.5 4328.1,4620.5 R12.2@4328.1,4650.5 ; R13.1 R12.2 R12.2@4328.1,4650.5
$2I8\PA15: J1.1 U4.47 | length 465.4
  Top Layer w10: v1(3969.9,4103.6) 3969.9,4123.6 4009.9,4163.6 U4.47
  Bottom Layer w10: J1.1 3969.9,3762.5 v1(3969.9,4103.6)
$2I8\PC9: J1.2 U4.49 | length 480.4
  Top Layer w10: v1(4101.3,4012.6) 4121.3,4032.6 U4.49
  Bottom Layer w10: J1.2 4011.3,3703.8 4011.3,3922.6 v1(4101.3,4012.6)
$2I8\PD0: J1.3 U4.50 | length 588.5
  Top Layer w10: v1(4130.9,3992.6) 4140.9,4002.6 U4.50
  Bottom Layer w10: J1.3 4030.9,3623.5 4030.9,3892.6 v1(4130.9,3992.6)
$2I8\power_+3.3V: C5.1 C6.1 C7.1 C8.1 D6.2 J4.3 J5.3 SW3.2 U4.6 U4.7 U4.8
$2I8\POWER_+3.3V:  | length 2759.4
  Top Layer w10: 4492.3,4242.3 4498.2,4246.8 ; 4492.3,4281.7 4492.3,4262 4498.2,4256.1 4498.2,4246.8 ; v1(4538.2,4256.8) 4518.2,4256.8 4508.2,4246.8 4498.2,4246.8 ; v1(4628.2,4246.8) 4648.2,4246.8 ; 4648.2,4154.3 4648.2,4216.1 4648.2,4276.8 4648.6,4277.2 4648.6,4338.6 4637.1,4350.1 4637.1,4458.6 4647.1,4468.6 4697.1,4468.6 4777,4388.7 4777,4298.7 4797,4278.7 4847,4278.7 4907,4338.7 4937,4338.7 4967,4368.7 4967,4428.7 5087,4548.7 5087.4,4549.2 v1(5129.2,4549.2) ; v1(5199.2,4549.2) 5283.6,4549.2 5373.6,4639.2
  Bottom Layer w10: 3871.4,4436.8 4408.2,4436.8 ; 4409.1,4856.3 4408.2,4855.5 4408.2,4416.8 4538.2,4286.8 v1(4538.2,4256.8) 4548.2,4246.8 v1(4628.2,4246.8) ; v1(5129.2,4549.2) v1(5199.2,4549.2)
$2I8\power_+5V: D9.1 J2.A4 J2.A9 J2.B4 J2.B9
$2I8\POWER_+5V:  | length 516.4
  Top Layer w10: 3677,4070.1 3647,4070.1 3583.4,4133.6 3583.4,4223 3613.4,4253 3667,4253 3677,4263 3710.5,4263 3720.5,4273 3720.5,4401 3705.4,4416.1
$2I8\power_+BATT: C4.1 R3.1 R22.1 U3.8
$2I8\POWER_+BATT:  | length 906.1
  Top Layer w10: 4336,3929.1 4358.1,3907 4805.5,3907 4825.5,3927 ; 4844.7,3831.1 4825.5,3850.3 4825.5,4057 4855.5,4087 4878.9,4087 4878.9,4115.6 4929.1,4165.7
$2I8\power_GND: BZ1.2 C4.2 C5.2 C6.2 C7.2 C8.2 C11.1 C12.2 C15.2 C16.1 C17.2 C18.2 C19.2 D5.2 D9.2 D10.2 D11.2 D14.2 D15.2 J1.4 J2.A1 J2.A12 J2.B1 J2.B12 J2.S1 J3.R J3.S J4.4 J5.4 R4.2 R6.1 R9.1 R13.2 R14.2 R15.2 R17.2 R21.2 R23.2 SW2.2 SW4.C SW4.MP SW4.S2 SW5.1 U3.4 U4.9
$2I8\POWER_GND:  | length 9078.7
  Top Layer w10: 3472.2,4419.7 3476.4,4415.6 3476.4,4336.6 ; 3640.9,3996.5 3677,4032.5 3677,4038.6 3818.3,3897.2 3865.3,3897.2 3905.3,3937.2 ; 3677,4294.5 3677,4300.6 3640.9,4336.6 3640.9,4389.9 3667.2,4416.1 3697.2,4446.1 3717.2,4446.1 3769.7,4393.7 3769.7,4202.6 ; 3747.2,4416.1 3750.8,4416.1 3871.3,4536.6 3950,4536.6 4010,4596.6 4034.2,4596.6 4036.4,4598.8 ; v1(3820.9,4136.6) 3796.7,4112.6 3796.7,4045.9 3845.3,3997.2 3905.3,3937.2 ; 3910.4,3929.5 3905.3,3937.2 ; 3982.3,5228.7 4179.1,5031.9 ; 4011.3,4596.6 4001.3,4606.6 4001.3,4692.6 4035.4,4726.8 4065.4,4696.8 4244.6,4696.8 4271.7,4723.8 4301.7,4753.8 4321.7,4753.8 4331.7,4763.8 ; 4138.4,3948 4105.4,3981 4022.6,3981 4012.6,3971 ; 4161.4,3603.5 4198.6,3640.7 4204.2,3640.7 ; 4194.2,3830.7 4214.2,3810.7 4214.2,3650.7 4204.2,3640.7 ; 4309.1,4856.3 4331.7,4833.7 4331.7,4763.8 ; 4402.6,4724.8 4363.5,4763.8 4331.7,4763.8 ; v1(4443.9,4271.4) 4433.9,4261.4 4423.9,4261.4 4413.9,4271.4 4413.9,4291.4 4423.9,4301.4 4492.3,4301.4 ; 4456.7,3383.1 4204.2,3635.6 4204.2,3640.7 ; 4456.7,3824 4450,3830.7 4014.2,3830.7 3984.2,3860.7 3984.2,3910.7 4014.2,3940.7 4012.6,3942.3 4012.6,3971 ; 4530.5,4056.9 4496.7,4023.1 4496.7,3964 v1(4526.7,3934) 4681.1,3934 4684.1,3937 4704.1,3937 4744.1,3977 4744.1,4119.5 4709.3,4154.3 4709.3,4216.1 4739.3,4246.1 ; 4676.4,4432.6 4709.6,4399.3 4709.6,4338.6 4679.3,4308.2 v1(4679.3,4306.8) 4709.3,4276.8 4739.3,4246.8 4739.3,4246.1 ; 4732.3,3702 4734.4,3702 4919.7,3516.7 5020.9,3516.7 5022.8,3514.8 5052.8,3544.8 5052.8,3599.3 5024.8,3627.4 ; 5049.1,4226.8 5049.1,4433.9 5209.1,4593.9 5209.1,4634.1 5214.2,4639.2 5278.6,4639.2 5368.6,4729.2 5368.6,4794.3 5339.3,4823.6 5349.3,4833.6 5349.3,4895 5356.9,4902.7 ; 5228,3965 5122.5,4070.4 5122.5,4194.5 5090.3,4226.8 4929.1,4226.8 4909.4,4207.1 4822.8,4207.1 4783.8,4246.1 4739.3,4246.1 ; 5349.3,4853.6 5433.7,4853.6 5438.2,4858.1 ; 3905.3,3937.2 3908.9,3937.2 3972.6,4001 3982.6,4001 4012.6,3971
  Bottom Layer w10: 3476.4,3996.5 3640.9,3996.5 ; 3476.4,4336.6 3640.9,4336.6 3640.9,4316.6 v1(3820.9,4136.6) ; 3961.4,3453.9 4111,3603.5 4161.4,3603.5 ; 4179.1,5031.9 4309.1,4902 4309.1,4856.3 ; v1(4443.9,4271.4) 4493.9,4221.4 4643.9,4221.4 4653.9,4231.4 4653.9,4281.4 v1(4679.3,4306.8) ; 4456.7,3824 4526.7,3894 ; v1(4526.7,3934) 4526.7,3894 ; 4732.3,3702 4540.2,3894 4526.7,3894
$2I8\power_VBUS: R20.1
$2I8\R1: SW4.B U4.53 | length 603.8
  Top Layer w10: v1(4190,3932.6) 4190,3982.6 4200,3992.6 U4.53
  Bottom Layer w10: SW4.B 4220,3563.7 4220,3902.6 v1(4190,3932.6)
$2I8\R2: SW4.A U4.52 | length 374.8
  Top Layer w10: v1(4160.3,3982.6) 4180.3,4002.6 U4.52
  Bottom Layer w10: v1(4160.3,3982.6) 4160.3,3703.1 SW4.A
$2I8\SWDIO: J5.1 U4.45 | length 204.7
  Top Layer w10: J5.1 3876.3,4236.6 3929.9,4183 3989.9,4183 4009.9,4203 U4.45
$2I8\TRIGGER: C16.2 D14.1 J3.T SW5.2 U4.29 | length 2351.2
  Top Layer w10: v1(4065.4,4631.9) 4065.4,4471.9 4092.4,4445 4152.4,4445 4182.4,4475 4182.4,4512.9 U4.29 ; v1(4102.4,4215) 4102.4,4445 ; v1(4622.4,3875) 4736.7,3875 SW5.2 4998.4,3691.9 D14.1 4994.8,3635.6 4994.8,3603.8 C16.2
  Bottom Layer w10: J3.T 4065.4,4751.9 v1(4065.4,4631.9) ; v1(4102.4,4215) 4172.4,4145 4352.4,4145 v1(4622.4,3875)
$2I8\USB_SENSE: C18.1 R20.2 R21.1 U4.48 | length 240.7
  Top Layer w10: R21.1 3912.6,3999.6 R20.2@3912.6,4062 ; R20.2 R20.2@3912.6,4062 ; U4.48 4045.5,4134.8 C18.1 R20.2@3912.6,4062
$2I8\~{RESET}: C11.2 SW2.1 U4.12 | length 1223.3
  Top Layer w10: U4.12 v1(4555.9,4360.4) ; v1(5095.9,4361.2) 5198.7,4464 SW2.1 5268.6,4464 5438.6,4634 5438.6,4796.6 C11.2
  Bottom Layer w10: v1(4555.9,4360.4) 5095.9,4360.4 v1(5095.9,4361.2)
GND: probe.2 probe.3 probe.4 | length 623.9
  Bottom Layer w10: probe.3@4702.1,5216.6 4800.5,5118.2 probe.2 5001.3,5216.6 probe.4
pads on no net: H1. H2. H3. H4. H5. J2. J2.A8 J2.B8 J3. J3.RN J3.TN SW1.1 U4.2 U4.3 U4.4 U4.5 U4.10 U4.11 U4.13 U4.16 U4.18 U4.19 U4.20 U4.23 U4.24 U4.25 U4.26 U4.27 U4.33 U4.34 U4.35 U4.36 U4.37 U4.38 U4.39 U4.40 U4.41 U4.42 U4.51 U4.55 U4.56 U4.57 U4.58 U4.59 U4.60 U4.61 U4.62 U4.63 U4.64
copper on no net: | length 41988.9
  Top Layer w7.9: 3503.5,4543.3 3568.5,4608.3 3574.4,4608.3 ; 3503.7,4617.1 3503.5,4617.1 ; 3521.9,4617.1 3503.5,4617.1 ; 3537.2,4419.7 3537.2,4317 3638.5,4215.7 3677,4215.7 ; 3574.4,4543.3 3648.2,4543.3 3649.8,4541.7 ; 3576.8,4368.5 3608.7,4336.6 3640.9,4336.6 ; 3640.9,3996.5 3640.9,4002.6 3677,4038.6 ; 3653.1,5006.8 3653.1,4915.4 3719.7,4848.8 ; 3667.2,4416.1 3640.9,4389.9 3640.9,4336.6 ; 3677,4097.6 3615,4097.6 3576.8,4059.4 3576.8,3970.9 3618.1,3929.5 3845.5,3929.5 ; 3677,4137 3715.4,4137 3723.6,4145.2 ; 3677,4156.7 3638.5,4156.7 3630.7,4164.5 3630.7,4188.3 3638.5,4196.1 3677,4196.1 3729.9,4196.1 3761.6,4164.4 3769.7,4164.4 ; 3677,4176.4 3715.4,4176.4 3723.6,4168.2 3723.6,4161.8 3723.6,4145.2 ; 3677,4294.5 3640.9,4330.5 3640.9,4336.6 ; 3715.7,4677.2 3710.8,4672.2 3710.8,4605.1 3710.8,4494.3 3727.4,4477.8 3753.9,4477.8 ; 3748,4070.1 3732.3,4070.1 3747.2,4070.1 3748.4,4068.9 3839.8,4068.9 3845.3,4063.4 ; 3753.9,4542.7 3753.9,4543.7 3826.4,4616.1 3902.8,4616.1 3915.4,4628.7 3915.4,4664.6 3889.8,4690.2 3837.5,4690.2 3794.5,4733.2 3794.5,4759.3 ; 3757.1,4834.6 3757.1,4848.8 ; 3765.7,4113.4 3777.8,4113.4 ; 3769,4164.4 3778.6,4154.7 3922.8,4154.7 4010.4,4242.3 4045.5,4242.3 ; 3785.4,5031.9 3785.4,5069.3 3849.2,5133.1 4192.1,5133.1 4222,5103.1 4222,4665 4180.3,4623.2 4180.3,4464.6 4215.4,4429.5 4215.4,4280.8 ; 3787.6,4752.4 3794.5,4759.3 ; 3794.5,4848.8 3794.5,4822.7 3782.7,4810.9 3720,4810.9 3624,4715 3624,4673.2 3603.1,4652.4 3538.8,4652.4 3503.5,4617.1 ; 3796.7,4112.6 3910.6,4112.6 3912.6,4114.6 3928,4099.2 4015,4099.2 4018.9,4103.1 ; 3797.2,4756.5 3794.5,4759.3 ; 3871.3,4336.6 3881.5,4336.6 4009.8,4465 4084.6,4465 4145.7,4403.9 4145.7,4377.6 4145.7,4233.5 4095.3,4183.1 4045.5,4183.1 ; 3898.8,4535.8 3902.8,4539.8 ; 3910.2,3997.2 3910.2,4063.4 ; 3910.4,3929.5 3937,3929.5 3972.6,3965.2 3972.6,4001 ; 3911.6,4062 3972.6,4062 4021.9,4062 4045.5,4085.6 4045.5,4143.7 ; 3966.1,4122.8 4006.7,4163.4 4045.5,4163.4 ; 4014.2,3879.7 4051.8,3917.3 4073.4,3917.3 ; 4035.4,4661.8 4070.9,4661.8 ; 4045.5,4203 4081.8,4203 4110.2,4231.4 4110.2,4236.6 ; 4045.5,4222.6 4013.2,4222.6 3929.5,4139 3784.8,4139 3758.5,4112.6 3725.9,4145.2 3723.6,4145.2 ; 4061,4059.4 4061,4039.8 4061.2,4040 4061.2,4108.2 4156.7,4203.6 4156.7,4204.3 4179.1,4226.8 ; 4086.6,4588 4097.4,4598.8 ; 4090.6,4649 4102.4,4660.8 4101.4,4661.8 4070.9,4661.8 ; 4102.4,4725.8 4102.4,4772 4106.3,4776 ; 4115.4,3996.1 4121.3,4002 4121.3,4067.9 ; 4121.3,4514.8 4121.3,4557.5 4097.4,4581.3 4097.4,4598.8 ; 4140.6,4116.9 4140.2,4116.5 4140.2,4068.7 4140.9,4067.9 ; 4140.9,4514.8 4140.9,4653.5 4174.8,4687.4 4174.8,4709.8 ; 4160.6,4514.8 4160.6,4644.1 4198.4,4681.9 ; 4180.3,4067.9 4180.3,3981.5 4196.9,3965 ; 4200,4067.9 4200,4009.1 4204.7,4004.3 ; 4200,4514.8 4200,4482.9 4244.9,4438 4244.9,4255.1 4091.7,4102 4091.7,3966.3 4073.4,3948 4073.4,3917.3 ; 4219.7,4067.9 4219.7,4032.7 4240.2,4012.2 ; 4271.1,3929.1 4210,3868.1 4139.4,3868.1 4090.2,3917.3 4073.4,3917.3 ; 4273.2,5207.9 4348,5207.9 4407.5,5207.9 4468.9,5207.9 4564.6,5207.9 ; 4275.6,4662.8 4271.7,4662.8 ; 4318.1,4514.8 4318.1,4591.7 4271.7,4638.2 4271.7,4662.8 ; 4337.6,4661.8 4337.6,4693.3 ; 4337.6,4724.8 4337.6,4693.3 ; 4337.8,4514.8 4337.8,4482.9 4377.6,4443.1 4377.6,4206.9 4485.7,4098.8 4559.5,4098.8 4602.4,4056 ; 4348,5062.2 4469.7,4940.6 4565,4940.6 ; 4401.2,4261.8 4420.9,4281.5 4492.3,4281.5 4591.5,4281.5 4648.6,4338.6 ; 4402.6,4661.8 4433.1,4661.8 4441.7,4670.5 4441.7,4692.5 ; 4416.5,4514.8 4417.3,4514 4417.3,4449.2 ; 4418.5,4346.9 4418.5,4343.2 4460.5,4301.2 4492.3,4301.2 4559.4,4301.2 4593.7,4335.4 4593.7,4340.2 ; 4419.7,4124 4447.2,4096.5 4447.2,4094.9 ; 4432.7,4261.8 4492.3,4261.8 4602.6,4261.8 ; 4492.3,4143.7 4569.3,4143.7 4570.9,4142.1 ; 4492.3,4242.1 4560.4,4242.1 4569.8,4232.8 4648.2,4154.3 ; 4492.3,4360.2 4547.2,4360.2 ; 4492.3,4399.6 4533.5,4399.6 4548.8,4415 4548.8,4441.9 4523,4467.7 4487.4,4467.7 4470.1,4485 4470.1,4564.6 4511.8,4606.3 4511.8,4664.6 ; 4492.3,4419.3 4460.5,4419.3 4448.4,4431.3 4448.4,4574 4465.4,4591 4465.4,4679.8 4512,4726.4 ; 4524.6,4502.4 4524.6,4496.3 4648.4,4372.4 4755.5,4372.4 4779.1,4348.8 4779.1,4260.6 4742.5,4224 4742.5,4070.1 4709.4,4037 4684.1,4037 ; 4530.5,3985 4601.5,3985 4602.4,3984.2 4627.9,3984.2 4628,3984.3 4639.4,3984.3 4642.1,3987 4684.1,3987 ; 4564.6,5062.2 4564.6,4940.9 4565,4940.6 ; 4564.6,5353.5 4564.6,5207.9 ; 4576.8,4664.6 4585,4656.3 4697.7,4656.3 4759.1,4594.9 ; 4577,4726.4 4585,4726.4 4637.8,4673.6 4759.1,4673.6 4718.5,4714.2 4718.5,4798.8 4759.1,4839.4 ; 4596.5,4502.4 4674.3,4502.4 4676.4,4504.4 4716.4,4504.4 4716.5,4504.3 ; 4599.4,4450 4613.8,4450 4617.7,4453.9 ; 4612.2,4106.7 4622.5,4117 4671.9,4117 4709.3,4154.3 ; 4648.2,4216.1 4602.6,4261.8 ; 4648.2,4276.8 4617.5,4276.8 4602.6,4261.8 ; 4684.1,4087 4670.4,4087 4633.8,4050.4 4633.8,4023.6 4644.1,4013.3 4724.1,4013.3 4892.5,4181.8 4892.5,4270.9 4929.1,4307.5 ; 4709.8,4153.7 4709.3,4154.3 ; 4714.6,4502.4 4716.5,4504.3 ; 4734.3,5031.9 4734.3,5067.7 ; 4746.5,4337 4744.9,4338.6 4709.6,4338.6 4709.6,4154.7 4709.3,4154.3 ; 4755.7,4590.6 4759,4593.9 4759,4625.4 ; 4755.7,4757.1 4759.1,4753.7 4759.1,4721.9 ; 4757.9,4503.3 4756.9,4504.3 4716.5,4504.3 ; 4766.9,4205.9 4768.5,4207.5 4868.9,4207.5 ; 4822.8,4321.3 4822.8,4402 4795.3,4429.5 4794,4430.8 4794,4869.2 4794.1,4869.3 4794.1,4883.1 4789.8,4887.4 4828.3,4887.4 4828.7,4887 4881.4,4887 4890.8,4877.6 ; 4827,4594.9 4958.1,4594.9 5004.3,4548.7 ; 4827,4673.6 5081.6,4673.6 ; 4827,4757.1 5004.1,4757.1 ; 4827,4839.4 5045.3,4839.4 5086.8,4797.9 ; 4832.7,4503.3 4929.1,4406.9 4929.1,4379.3 ; 4863.4,3742.1 4869.5,3742.1 4919.7,3691.9 ; 4878.9,3937 4916.5,3899.4 4916.5,3831.1 5050.7,3965.3 5050.7,4194.5 ; 4943.3,4430.3 5040.6,4333.1 5347.2,4333.1 5373.6,4359.4 5373.6,4464 ; 4962.7,4877.6 4899.7,4940.6 4565,4940.6 ; 5002.8,4548.7 5004.3,4548.7 ; 5004.1,4797.9 5004.1,4757.1 ; 5004.2,4633.4 5004.3,4633.3 5004.3,4548.7 ; 5004.2,4714.9 5004.1,4715 5004.1,4757.1 ; 5022.8,3575.8 4958.9,3639.8 4958.9,3652.8 4919.7,3691.9 ; 5024.8,3665.6 4999.8,3665.6 4973.4,3691.9 4919.7,3691.9 ; 5086.9,4633.4 5086.9,4672.4 5086.9,4714.9 ; 5091.3,4798.4 5090.8,4797.9 5086.8,4797.9 ; 5128,5002 5128,5031.9 ; 5162.2,4371.3 5162.2,4412 5214.2,4464 5266.3,4464 5322.8,4520.5 5380.3,4520.5 5438.2,4578.3 5438.2,4797 ; 5246.1,3752.4 5246.1,3824 ; 5257.1,4739 5145.7,4739 5086.8,4797.9 ; 5264.5,4823.6 5264.5,4802.5 5328,4739 5339.8,4739 ; 5267.7,4823.4 5267.9,4823.6 5267.9,4893.9 5268.3,4894.3 ; 5268.3,4959.3 5299.3,4959.3 5356.9,5016.8 5291.8,5016.8 5167.7,5140.9 4669.7,5140.9 4602.8,5207.9 4564.6,5207.9 ; 4070.9,4661.8 4070.9,4630.3 4097.4,4603.7 4097.4,4598.8 ; 4271.7,4662.8 4271.7,4669.7 4295.3,4693.3 4337.6,4693.3
  Top Layer w23.6: 3488.6,3720.9 3476.8,3720.9 3596.5,3720.9 3774.1,3543.2 3774.1,3451.2 ; 3505.1,4808.3 3505.9,4807.5 3612.2,4807.5 3653.5,4848.8 3719.7,4848.8 ; 3677,4070.1 3732.3,4070.1 ; 3677,4263 3732.3,4263 3732.3,4344.9 3704.7,4372.4 3704.7,4415.5 3705.4,4416.1 3705.4,4428.1 3649.8,4483.7 3649.8,4541.7 3649.8,4605.1 3649.8,4689.4 3719.7,4759.3 3754.5,4759.3 3755.1,4758.7 ; 3719.2,4668.4 3719.2,4677.2 3721.3,4677.2 ; 3766.9,4602.8 3766.9,4633.1 3766.9,4634.6 3787.1,4654.8 3787.1,4677.2 3801.6,4677.2 3825.2,4653.5 3869.8,4653.5 3870.2,4653.1 ; 3846.5,3533.9 3846.5,3512.2 3847.9,3510.7 3847.9,3451.2 ; 3862.2,4847.6 3862.2,4875.6 3872,4885.4 ; 3872,4802.8 3952,4802.8 4020.6,4802.8 4026,4808.2 3959.7,4741.9 3959.7,4690.6 ; 3948,4845.7 3948,4881.5 3952,4885.4 ; 3994.5,4728 4034.3,4728 4035.4,4726.8 4036.2,4727.6 4036.2,4763 ; 4283.3,3981.9 4336,3929.1 ; 4335.4,3928.5 4336,3929.1 ; 4844.7,3831.1 4783.9,3891.9 ; 4878.9,3987 4878.9,4037 ; 4929.1,4165.7 4878.9,4115.6 4878.9,4087 4840.6,4087 4814.2,4060.6 4814.2,3922.2 4783.9,3891.9 ; 5087,4548.7 5148.3,4548.7 5174,4574.4 5352.8,4574.4 5354.7,4572.4 5374,4591.7 5374,4638.8 5373.6,4639.2 ; 4336,3929.1 4360.8,3904.4 4571.2,3904.4 4604.7,3870.9 4765.7,3870.9 4783.9,3889 4783.9,3891.9
  Bottom Layer w7.9: 3822.4,4802.4 3823.2,4803.1 3857.1,4803.1 3902.8,4848.8 3902.8,4874.4 ; 3871.3,4236.6 4110.2,4236.6 ; 3898.8,4435.8 3900.8,4437.8 ; 3961.4,3553.9 4006.7,3599.3 4006.7,3635.2 4006.7,3672.7 4006.7,3676.9 4054.6,3724.8 4063.8,3734 4063.8,3747.1 4063.8,3909.9 4140.2,3986.2 4140.2,4116.5 4140.6,4116.9 ; 3961.4,3653.9 4048,3740.6 4048,3928.7 4115.4,3996.1 ; 3961.4,3753.9 3961.4,4118.1 3966.1,4122.8 ; 4106.3,4776 4090.6,4776 4078,4788.6 4078,4843.3 4273.2,5038.6 4273.2,5207.9 ; 4145.7,4377.6 4170.5,4402.4 4915.4,4402.4 4943.3,4430.3 ; 4161.4,3505.1 4224.4,3568.1 4224.4,3984.7 4204.7,4004.3 ; 4161.4,3702 4196.9,3737.4 4196.9,3965 ; 4174.8,4709.8 4175.6,4710.6 4175.6,4728.7 4182.7,4735.8 4182.7,4854.6 4265.9,4937.8 4384.6,4937.8 4528.3,4937.8 4609.4,4856.7 ; 4198.4,4681.9 4198.4,4848 4272.4,4922 4444.1,4922 4509.4,4856.7 ; 4215.4,4280.8 4246.4,4280.8 4367.3,4159.8 4435.4,4159.8 4853.1,3742.1 4863.4,3742.1 ; 4240.2,4012.2 4240.2,3915.7 4240.2,3915.6 4240.2,3764.1 4429.9,3574.4 4663,3574.4 4732.3,3505.1 ; 4417.3,4449.2 4472.4,4504.3 4716.5,4504.3 ; 4441.7,4692.5 4444.9,4689.4 4574.8,4689.4 4689,4803.5 4689,4866.5 4710.2,4887.8 4789.4,4887.8 ; 4547.2,4360.2 4570.9,4383.9 5044.5,4383.9 5068.1,4360.2 5151.2,4360.2 5162.2,4371.3 ; 4570.9,4142.1 4574.8,4146 4933.1,4146 5228,3851.2 5228,3768.1 ; 4759.1,4625.4 4759.1,4721.9 ; 4794.1,4891.7 4794.1,4939.8 4734.3,4999.6 4734.3,5031.9 4734.3,5082.7 4880.3,5228.7 4931.1,5228.7 ; 4832.7,5031.9 4891.7,4972.8 4970.5,4972.8 5029.5,5031.9 ; 4965.7,5228.7 4931.1,5228.7 ; 5128,5002 5128,5031.9 ; 5128,5066.5 5128,5031.9 ; 5246.1,3752.4 5246.1,3833.1 ; 4931.1,5228.7 4983.5,5228.7 5128,5084.3 5128,5031.9
  Bottom Layer w23.6: 3528.7,4808.3 3601.6,4808.3 3651.2,4758.7 3651.2,4709.1 3694.5,4665.7 3694.5,4378.7 3773.6,4299.6 3773.6,3901.2 3675.2,3802.8 3675.2,3707.1 3816.9,3565.4 3816.9,3563.4 3846.5,3533.9 ; 3528.7,4887 3822.8,4887 3862.2,4847.6 3759.8,4847.6 3692.9,4780.7 3692.9,4715.7 3728,4680.7 3728,4389.8 3807.1,4310.7 3807.1,4177.6 3830.3,4154.3 4224.5,4154.3 4283.3,4095.6 4283.3,3981.9 ; 3732.3,4263 3734.3,4261 3734.3,4080.7 ; 3755.1,4758.7 3861,4758.7 3948,4845.7 ; 4409.4,4856.7 4409.4,4735 4321.7,4647.2 3781.1,4647.2 3766.9,4633.1 3766.9,4540.9 3875.2,4432.7 3875.2,4426 3889,4412.2 3895.7,4412.2 3972,4335.8 4316.9,4335.8 4390.9,4261.8 4432.7,4261.8 4570.5,4261.8 ; 4569.8,4232.8 4570.5,4233.5 4570.5,4261.8 ; 5354.7,4572.4 5343.3,4561 5343.3,4560.2 5299.6,4516.5 5299.6,4398.8 5162.6,4261.8 4570.5,4261.8

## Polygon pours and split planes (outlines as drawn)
no net on Top Layer (solid, remove dead copper, pour order 2): 3144.5,5642.5 5724,5584.3 5748.4,3000 3000,3079.1 3035.4,5496.5
no net on Bottom Layer (solid, remove dead copper, pour order 6): 3144.5,5642.5 5724,5584.3 5748.4,3000 3000,3079.1 3035.4,5496.5

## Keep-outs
Board Outline Layer:
  lines w5.9: 3726.4,5405.9 3570.9,5405.9 3560.1,5405.5 3549.4,5404.4 3538.8,5402.6 3528.4,5400.1 3518.1,5396.8 3508.1,5392.9 3498.4,5388.2 3489,5383 3480.1,5377.1 3471.5,5370.6 3463.4,5363.5 3455.8,5355.9 3448.7,5347.8 3442.2,5339.2 3436.3,5330.2 3431,5320.9 3426.4,5311.2 3422.5,5301.2 3419.2,5290.9 3416.7,5280.5 3414.9,5269.9 3413.8,5259.2 3413.4,5248.4 3413.4,3476.8 3413.8,3466 3414.9,3455.3 3416.7,3444.7 3419.2,3434.3 3422.5,3424 3426.4,3414 3431,3404.3 3436.3,3394.9 3442.2,3386 3448.7,3377.4 3455.8,3369.3 3463.4,3361.7 3471.5,3354.6 3480.1,3348.1 3489,3342.2 3498.4,3336.9 3508.1,3332.3 3518.1,3328.4 3528.4,3325.1 3538.8,3322.6 3549.4,3320.8 3560.1,3319.7 3570.9,3319.3 5342.5,3319.3 5353.3,3319.7 5364,3320.8 5374.6,3322.6 5385,3325.1 5395.3,3328.4 5405.3,3332.3 5415,3336.9 5424.3,3342.2 5433.3,3348.1 5441.9,3354.6 5450,3361.7 5457.6,3369.3 5464.7,3377.4 5471.2,3386 5477.1,3394.9 5482.3,3404.3 5487,3414 5490.9,3424 5494.2,3434.3 5496.7,3444.7 5498.5,3455.3 5499.6,3466 5500,3476.8 5500,5248.4 5499.6,5259.2 5498.5,5269.9 5496.7,5280.5 5494.2,5290.9 5490.9,5301.2 5487,5311.2 5482.3,5320.9 5477.1,5330.2 5471.2,5339.2 5464.7,5347.8 5457.6,5355.9 5450,5363.5 5441.9,5370.6 5433.3,5377.1 5424.3,5383 5415,5388.2 5405.3,5392.9 5395.3,5396.8 5385,5400.1 5374.6,5402.6 5364,5404.4 5353.3,5405.5 5342.5,5405.9 5187,5405.9 4238.2,5405.9

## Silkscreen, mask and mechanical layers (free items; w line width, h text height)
Top Silkscreen Layer:
  lines w3.9: 4061.4,4759.4 4095.3,4789.8
  lines w7.9: 4690.2,4805.9 4723.2,4828 ; 4720.5,4723.2 4730.3,4732.7
  text "OLED" at 4397.2,4943.3 h39.4
  text "RST" at 5215,4384.8 h59.1 r270
  text "BOOT" at 5373.6,4370.1 h59.1 r270
  text "TRIGGER" at 4813,3386.2 h59.1
Bottom Silkscreen Layer:
  text "BODY" at 4332.3,5176.7 h59.1
  text "PEDAL" at 3871.9,5106.3 h59.1
  text "PROBE" at 4821.2,5103.9 h59.1
  text "GND / 3v3 / SCL / SDA" at 4159.4,4856.1 h59.1 r90
  text "- GND" at 3820.9,4485.1 h39.4 r315
  text "- 3v3" at 3822.8,4386.7 h39.4 r315
  text "- SWCLK" at 3820.9,4272.4 h39.4 r315
  text "- SWDIO" at 3820.5,4174 h39.4 r315
  text "+-" at 3526.8,3726 h70.9 r270
  text "Based on / n3tcat's design / scd31.com" at 5240.2,3304.2 h39.4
